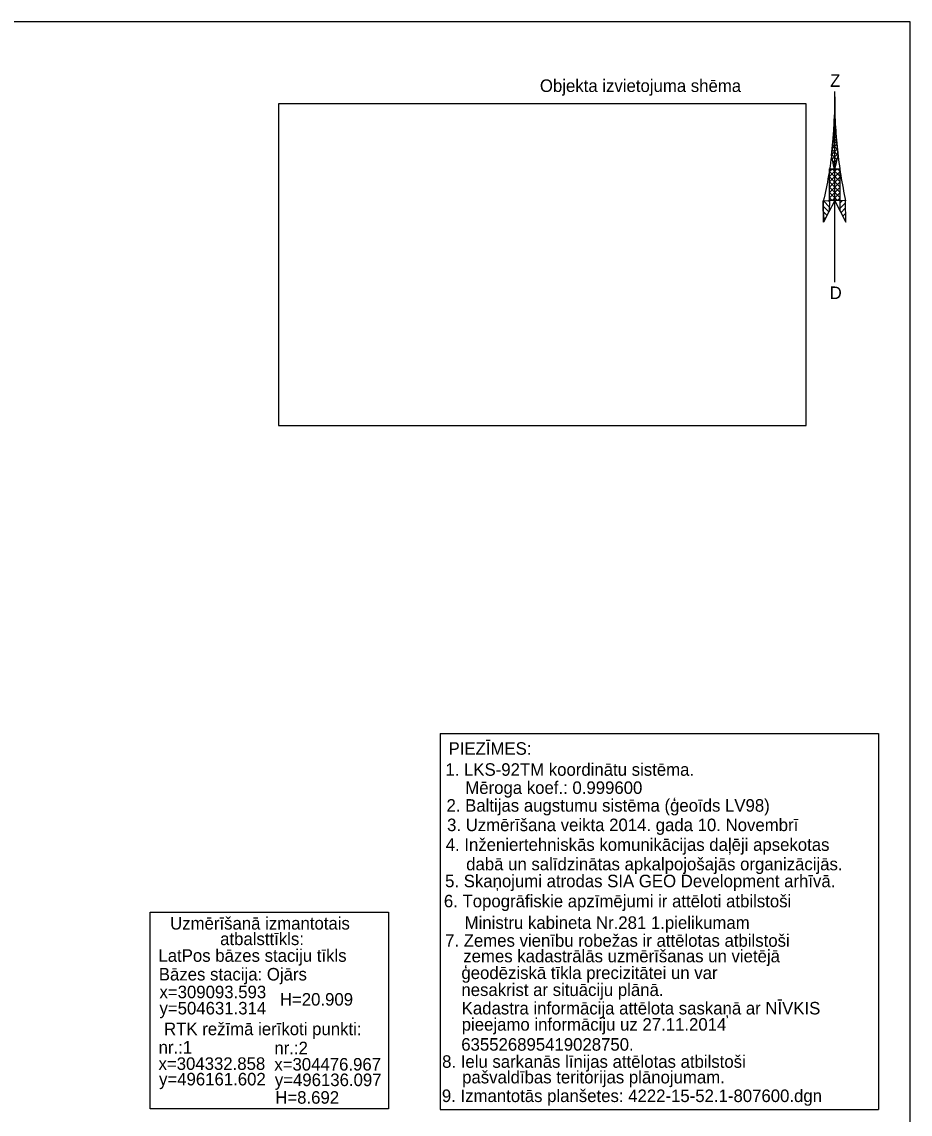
# Model space of a CAD drawing. Extents: x 496078 to 496285, y 304225 to 304369.
# Drawn here: x 496214.4 to 496285.3, y 304282 to 304369.1 of the extents above; entities that cross this region are included whole.
import ezdxf

# ---------------------------------------------------------------- set-up
doc = ezdxf.new("R2010")
doc.units = 0
doc.layers.add('RAMI_PLAN_####_TKST_#', color=7, linetype='Continuous')

msp = doc.modelspace()

# ---------------------------------------------------------------- linework, layer by layer
at = {"layer": 'RAMI_PLAN_####_TKST_#'}
for p, q in [((496285.321, 304369.101), (496089.321, 304369.101)), ((496285.321, 304225.145), (496285.321, 304369.101)), ((496279.289, 304363.534), (496279.289, 304348.332)), ((496279.226, 304360.444), (496279.291, 304361.681)), ((496279.291, 304361.681), (496279.313, 304361.682)), ((496279.293, 304361.682), (496279.317, 304361.657)), ((496279.313, 304361.682), (496279.37, 304360.517)), ((496279.246, 304360.814), (496279.351, 304360.919)), ((496279.249, 304360.88), (496279.36, 304360.77)), ((496279.267, 304361.259), (496279.333, 304361.322)), ((496279.27, 304361.282), (496279.336, 304361.215)), ((496279.155, 304359.498), (496279.226, 304360.444)), ((496279.186, 304359.909), (496279.402, 304360.126)), ((496279.199, 304360.085), (496279.424, 304359.861)), ((496279.219, 304360.365), (496279.37, 304360.517)), ((496279.228, 304360.478), (496279.387, 304360.322)), ((496279.37, 304360.517), (496279.491, 304359.024)), ((496279.04, 304358.454), (496279.155, 304359.498)), ((496279.048, 304358.503), (496279.498, 304358.955)), ((496279.092, 304358.925), (496279.549, 304358.468)), ((496279.098, 304358.977), (496279.466, 304359.342)), ((496279.133, 304359.308), (496279.498, 304358.94)), ((496279.15, 304359.449), (496279.433, 304359.734)), ((496279.17, 304359.693), (496279.46, 304359.402)), ((496279.491, 304359.024), (496279.555, 304358.427)), ((496279.287, 304357.329), (496279.04, 304358.454)), ((496279.051, 304358.544), (496279.479, 304358.117)), ((496279.11, 304358.143), (496279.539, 304358.572)), ((496279.131, 304358.043), (496279.397, 304357.775)), ((496279.186, 304357.799), (496279.471, 304358.083)), ((496279.555, 304358.427), (496279.287, 304357.329)), ((496278.874, 304354.847), (496278.895, 304357.373)), ((496278.89, 304356.755), (496279.509, 304357.373)), ((496278.895, 304357.373), (496279.702, 304357.372)), ((496278.895, 304357.179), (496279.087, 304357.372)), ((496279.108, 304357.373), (496279.704, 304356.78)), ((496279.25, 304357.501), (496279.312, 304357.437)), ((496279.261, 304357.451), (496279.335, 304357.525)), ((496279.53, 304357.372), (496279.702, 304357.203)), ((496279.702, 304357.372), (496279.708, 304354.844)), ((496278.879, 304355.477), (496279.704, 304356.302)), ((496278.883, 304355.902), (496279.704, 304356.723)), ((496278.887, 304356.327), (496279.702, 304357.146)), ((496278.887, 304356.327), (496279.705, 304355.509)), ((496278.89, 304356.746), (496279.705, 304355.933)), ((496278.895, 304357.166), (496279.704, 304356.355)), ((496278.875, 304355.051), (496279.705, 304355.88)), ((496278.877, 304355.49), (496279.526, 304354.844)), ((496278.883, 304355.908), (496279.708, 304355.085)), ((496279.093, 304354.846), (496279.705, 304355.458)), ((496278.39, 304354.812), (496278.874, 304354.847)), ((496278.39, 304354.812), (496278.412, 304353.125)), ((496278.412, 304353.125), (496278.39, 304354.812)), ((496278.394, 304354.81), (496278.872, 304354.33)), ((496278.412, 304353.125), (496279.303, 304354.834)), ((496278.785, 304354.841), (496278.874, 304354.751)), ((496278.874, 304354.847), (496278.871, 304354.005)), ((496278.874, 304355.073), (496279.102, 304354.845)), ((496279.708, 304354.844), (496278.874, 304354.847)), ((496279.303, 304354.834), (496280.19, 304353.126)), ((496279.511, 304354.845), (496279.706, 304355.036)), ((496279.704, 304354.209), (496280.17, 304354.676)), ((496279.708, 304354.844), (496279.705, 304354.051)), ((496279.706, 304354.633), (496279.91, 304354.84)), ((496280.167, 304354.834), (496279.708, 304354.844)), ((496280.19, 304353.126), (496280.167, 304354.834)), ((496280.19, 304353.126), (496280.167, 304354.834)), ((496278.396, 304354.383), (496278.839, 304353.944)), ((496278.401, 304353.955), (496278.693, 304353.665)), ((496278.871, 304354.005), (496278.412, 304353.125)), ((496279.705, 304354.051), (496280.19, 304353.126)), ((496279.797, 304353.877), (496280.174, 304354.257)), ((496279.94, 304353.6), (496280.179, 304353.84)), ((496278.408, 304353.528), (496278.549, 304353.388)), ((496278.413, 304353.132), (496278.422, 304353.14)), ((496280.084, 304353.323), (496280.186, 304353.423)), ((496280.19, 304353.128), (496280.19, 304353.128)), ((496247.806, 304312.332), (496247.807, 304282.338)), ((496247.806, 304312.332), (496282.807, 304312.332)), ((496282.807, 304312.332), (496282.807, 304282.338)), ((496224.688, 304298.074), (496243.684, 304298.074)), ((496224.688, 304282.39), (496224.688, 304298.074)), ((496243.684, 304298.074), (496243.684, 304282.39)), ((496243.684, 304282.39), (496224.688, 304282.39)), ((496247.807, 304282.338), (496282.807, 304282.338))]:
    msp.add_line(p, q, dxfattribs=at)
for points in [[(496279.29, 304363.532), (496279.296, 304363.274), (496279.3, 304363.016), (496279.303, 304362.757), (496279.303, 304362.499), (496279.302, 304362.241), (496279.298, 304361.982), (496279.293, 304361.723), (496279.285, 304361.465), (496279.275, 304361.206), (496279.264, 304360.948), (496279.25, 304360.689), (496279.235, 304360.43), (496279.217, 304360.172), (496279.198, 304359.914), (496279.176, 304359.656), (496279.152, 304359.398), (496279.127, 304359.14), (496279.099, 304358.882), (496279.07, 304358.625), (496279.038, 304358.368), (496279.004, 304358.111), (496278.969, 304357.854), (496278.931, 304357.598), (496278.892, 304357.342), (496278.85, 304357.086), (496278.807, 304356.831), (496278.762, 304356.577), (496278.714, 304356.322), (496278.665, 304356.068), (496278.614, 304355.815), (496278.56, 304355.562), (496278.505, 304355.31), (496278.448, 304355.058), (496278.389, 304354.807)], [(496279.29, 304363.532), (496279.288, 304363.275), (496279.288, 304363.017), (496279.289, 304362.76), (496279.293, 304362.502), (496279.298, 304362.245), (496279.304, 304361.987), (496279.313, 304361.73), (496279.322, 304361.472), (496279.334, 304361.215), (496279.347, 304360.957), (496279.362, 304360.7), (496279.379, 304360.442), (496279.397, 304360.185), (496279.417, 304359.928), (496279.439, 304359.671), (496279.463, 304359.414), (496279.488, 304359.157), (496279.514, 304358.9), (496279.543, 304358.644), (496279.573, 304358.388), (496279.604, 304358.132), (496279.638, 304357.876), (496279.673, 304357.62), (496279.709, 304357.365), (496279.748, 304357.11), (496279.788, 304356.856), (496279.829, 304356.601), (496279.873, 304356.347), (496279.918, 304356.093), (496279.964, 304355.84), (496280.012, 304355.587), (496280.062, 304355.335), (496280.114, 304355.082), (496280.167, 304354.831)]]:
    msp.add_lwpolyline(points, dxfattribs=at)
msp.add_lwpolyline([(496234.912, 304336.91), (496277.02, 304336.91), (496277.02, 304362.552), (496234.912, 304362.552)], close=True, dxfattribs=at)

# ---------------------------------------------------------------- texts
for s, p in [('Objekta izvietojuma shēma', (496255.778, 304363.506)), ('x=309093.593 ', (496225.422, 304291.214)), (' H=20.909', (496234.658, 304290.626)), ('y=504631.314', (496225.422, 304289.92))]:
    msp.add_text(s, height=1, dxfattribs=at).set_placement(p)
for s, rotation, p in [('Z', 359.99874, (496278.932, 304363.913)), ('D', 359.99874, (496278.896, 304346.989)), ('PIEZĪMES:', 0.00002, (496248.489, 304310.635)), ('1. LKS-92TM koordinātu sistēma. ', 0.00002, (496248.235, 304308.958)), ('Mēroga koef.: 0.999600', 0.00002, (496249.825, 304307.512)), ('2. Baltijas augstumu sistēma (ģeoīds LV98)', 0.00002, (496248.326, 304306.094)), ('3. Uzmērīšana veikta 2014. gada 10. Novembrī', 0.00002, (496248.369, 304304.542)), ('4. Inženiertehniskās komunikācijas daļēji apsekotas', 0.00002, (496248.259, 304302.968)), ('dabā un salīdzinātas apkalpojošajās organizācijās.', 0.00002, (496249.895, 304301.419)), ('5. Skaņojumi atrodas SIA GEO Development arhīvā.', 0.00002, (496248.211, 304300.066)), ('6. Topogrāfiskie apzīmējumi ir attēloti atbilstoši', 0.00002, (496248.114, 304298.466)), ('Uzmērīšanā izmantotais ', 0.00002, (496226.27, 304296.69)), ('    Ministru kabineta Nr.281 1.pielikumam', 0.00002, (496248.285, 304296.745)), ('atbalsttīkls:', 0.00002, (496230.261, 304295.451)), ('7. Zemes vienību robežas ir attēlotas atbilstoši', 0.00002, (496248.21, 304295.318)), ('LatPos bāzes staciju tīkls', 0.00002, (496225.337, 304294.119)), ('   zemes kadastrālās uzmērīšanas un vietējā', 0.00002, (496248.547, 304294.079)), ('Bāzes stacija: Ojārs', 0.00002, (496225.369, 304292.629)), ('   ģeodēziskā tīkla precizitātei un var ', 0.00002, (496248.399, 304292.744)), ('   nesakrist ar situāciju plānā.', 0.00002, (496248.399, 304291.39)), ('Kadastra informācija attēlota saskaņā ar NĪVKIS ', 0.00002, (496249.538, 304289.92)), ('RTK režīmā ierīkoti punkti:', 0.00002, (496225.786, 304288.267)), ('pieejamo informāciju uz 27.11.2014', 0.00002, (496249.538, 304288.626)), ('nr.:1', 0.00002, (496225.351, 304286.802)), ('nr.:2', 0.00002, (496234.589, 304286.747)), ('635526895419028750.', 0.00002, (496249.502, 304287.029)), ('8. Ielu sarkanās līnijas attēlotas atbilstoši', 359.99966, (496247.973, 304285.663)), ('x=304332.858', 0.00002, (496225.346, 304285.498)), ('x=304476.967', 0.00002, (496234.584, 304285.444)), ('y=496161.602', 0.00002, (496225.387, 304284.259)), ('y=496136.097', 0.00002, (496234.626, 304284.204)), (' pašvaldības teritorijas plānojumam.', 359.99966, (496249.202, 304284.419)), ('9. Izmantotās planšetes: 4222-15-52.1-807600.dgn', 359.99966, (496247.955, 304282.932)), ('H=8.692', 0.00002, (496234.66, 304282.8))]:
    msp.add_text(s, height=1, rotation=rotation, dxfattribs=at).set_placement(p)

doc.saveas('drawing.dxf')
